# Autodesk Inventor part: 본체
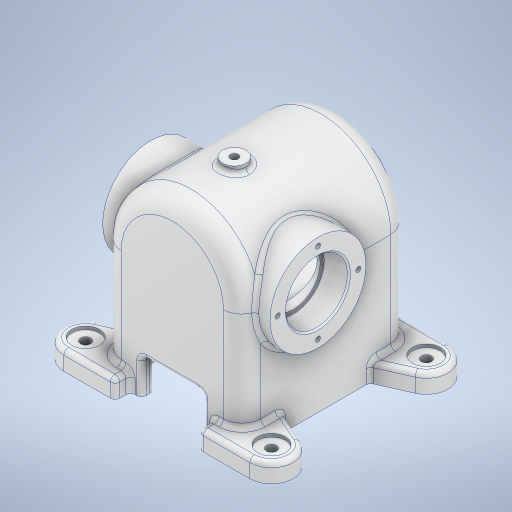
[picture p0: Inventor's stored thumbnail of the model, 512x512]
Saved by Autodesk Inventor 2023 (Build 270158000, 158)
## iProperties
Created: 2024-09
Part Number: 본체
Material: 알루미늄 6061
Document SubType Name: Modeling
Designer: asung
Density: 2.7 g/cm^3
Appearance: 알루미늄 - 평지
Mass: 1380.46 g
Surface Area: 1145.88 cm^2
Volume: 511.281 cm^3
Author: asung
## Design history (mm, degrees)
sketch "스케치1" dims "d0" = 90
  geometry: L1 (-45, 0)-(45, 0); L2 (45, 0)-(45, -76); L3 (45, -76)-(-45, -76); L4 (-45, -76)-(-45, 0); L5 (-20, -76)-(20, -76); L6 (20, -76)-(20, -53); L7 (20, -53)-(-20, -53); L8 (-20, -53)-(-20, -76); 5 further points
  constraints: 16 end point, 4 parallel, 2 horizontal, 2 midpoint, 2 perpendicular, 1 coincident, 1 point on line, 1 vertical, 3 other
  dimensions: "d1" = 90 distance of L2.end L3.end; "d2" = 76 distance of L1.end L2.end; "d3" = 40 distance of L7.end L6.end; "d4" = 23 distance of L6.end L5.end
extrude "돌출1" new body sketch "스케치1" stored distance "d5" = 108; taper "d6" = 0 deg
sketch "스케치2"
  geometry: C1 r 28.5 at (0, 0); 1 further point
  constraints: 1 centre point, 1 coincident
  dimensions: "d7" = 57 diameter of C1
extrude "돌출2" join sketch "스케치2" distance "d8" = 6; taper "d9" = 0 deg
fillet "모깎기1" dims "d10" = 12
fillet "모깎기2" dims "d11" = 3
node "작업 평면1"
sketch "스케치3"
  geometry: L1 (12, 109)-(12, 23) reference; L2 (12, 23)-(-96, 23) reference; L3 (-96, 23)-(-96, 44.5) reference; L4 (-99, 47.5)-(-102, 47.5) reference; L5 (-102, 47.5)-(-102, 104.5) reference; L6 (-102, 104.5)-(-99, 104.5) reference; L7 (-96, 107.5)-(-96, 109) reference; L8 (-84, 121)-(0, 121) reference; L9 (-102, 76)-(12, 76); L10 (3, 76)-(3, 109); L11 (0, 112)-(-84, 112); L12 (-87, 109)-(-87, 76); A1 r 12 centre (0, 109) between (12, 109) and (0, 121) reference; A2 r 3 centre (-99, 44.5) between (-96, 44.5) and (-99, 47.5) reference; A3 r 3 centre (-99, 107.5) between (-99, 104.5) and (-96, 107.5) reference; A4 r 12 centre (-84, 109) between (-84, 121) and (-96, 109) reference; A5 r 3 centre (0, 109) between (3, 109) and (0, 112); A6 r 3 centre (-84, 109) between (-84, 112) and (-87, 109); 1 further point
  constraints: 8 end point, 4 point on circle, 4 tangent, 3 point on line, 2 centre point, 2 perpendicular, 1 equal radius, 1 horizontal, 1 midpoint, 1 vertical
  dimensions: "d12" = 9 distance between parallel lines of L8 L11; "d13" = 9 distance between parallel lines of L10 L1; "d14" = 9 distance from line of L7.end L12; "d15" = 3 radius of A5
revolve "회전1" sketch "스케치3" stored, may be unused: angle "d16" = 90 deg
sketch "스케치4"
  geometry: C1 r 28.5 at (0, 0) reference; 2 further points
  constraints: 1 coincident
hole "구멍1" sketch "스케치4" at (0, 0) diameter "d17" = 33; stored, may be unused: countersink angle "d21" = 90 deg, drill point angle "d23" = 118 deg; dims "d18" = 7, "d19" = 4, "d20" = 2, "d22" = 25
chamfer "모따기1" distance "d24" = 1; stored, may be unused: second distance "d25" = 2, angle "d26" = 45 deg
node "작업 평면2"
sketch "스케치5"
  geometry: L1 (-102, 104.5)-(-102, 47.5) reference; C1 r 31 at (-28, 76)
  constraints: 1 centre point
  dimensions: "d28" = 62 diameter of C1; "d127" = 74 distance from line of L1 C1.centre
extrude "돌출3" join sketch "스케치5" stored distance "d29" = 10; taper "d30" = 0 deg
sketch "스케치9" dims "d60" = 46
  geometry: 3 further points
  constraints: 2 vertical alignment, 1 coincident, 2 other
hole "구멍5" sketch "스케치9" at (0, 23) diameter "d61" = 3.242; stored, may be unused: countersink angle "d65" = 90 deg, drill point angle "d67" = 118 deg; dims "d62" = 8, "d63" = 4, "d64" = 2, "d66" = 10
node "작업 평면3"
sketch "스케치10"
  geometry: L1 (-48.5, -6)-(8.5, -6) reference; C1 r 7.5 at (-20, 68); 1 further point
  constraints: 1 centre point, 1 vertical alignment
  dimensions: "d72" = 15 diameter of C1; "d73" = 74 distance from line of L1 C1.centre
extrude "돌출4" join sketch "스케치10" stored distance "d74" = 10; taper "d75" = 0 deg
fillet "모깎기4" dims "d76" = 3
node "작업 평면4"
sketch "스케치11"
  geometry: L1 (-54, -27.659)-(-54, 27.659) reference; L2 (-54, 27.659)-(-35.496, 27.659) reference; L3 (45, -27.659)-(45, -76) reference; L4 (45, -76)-(20, -76) reference; L5 (20, -76)-(20, -53) reference; L6 (20, -53)-(-20, -53) reference; L7 (-20, -53)-(-20, -76) reference; L8 (-20, -76)-(-45, -76) reference; L9 (-45, -76)-(-45, -27.659) reference; L10 (-45, -27.659)-(-54, -27.659) reference; L11 (-36, -27)-(-36, -76); L12 (36, -27)-(36, -76); L13 (54, 27.659)-(54, -27.659) reference; L14 (54, -27.659)-(45, -27.659) reference; L15 (35.496, 27.659)-(54, 27.659) reference; C1 r 36 at (0, 0) reference; A1 r 45 centre (0, 0) between (-36, -27) and (36, -27); A2 r 45 centre (0, 0) between (35.496, 27.659) and (-35.496, 27.659) reference; 1 further point
  constraints: 4 end point, 2 perpendicular, 2 point on circle, 2 point on line, 1 centre point, 1 coincident
  dimensions: "d78" = 90 diameter of A1; "d79" = 9 distance between parallel lines of L11 L9; "d80" = 9 distance between parallel lines of L3 L12
extrude "돌출5" cut sketch "스케치11" stored distance "d81" = 91; taper "d82" = 0 deg
fillet "모깎기6" dims "d83" = 3
fillet "모깎기7" dims "d84" = 3
sketch "스케치12" dims "d87" = 28
  geometry: L1 (-41, 10)-(107, 10); L2 (107, 10)-(107, -118); L3 (107, -118)-(-41, -118); L4 (-41, -118)-(-41, 10); L5 (-41, 10)-(107, -118); L6 (107, 10)-(-41, -118); L7 (53, -8.5)-(66, -8.5) reference; L8 (69, -11.5)-(69, -96.5) reference; L9 (66, -99.5)-(53, -99.5) reference; L10 (53, -108)-(53, -99.5) reference; L11 (66, -108)-(53, -108) reference; L12 (78, -96)-(78, -12) reference; L13 (53, 0)-(66, 0) reference; L14 (53, -8.5)-(53, 0) reference; L15 (0, -8.5)-(13, -8.5) reference; L16 (13, -8.5)-(13, 0) reference; L17 (0, 0)-(13, 0) reference; L18 (-12, -12)-(-12, -96) reference; L19 (13, -108)-(0, -108) reference; L20 (13, -108)-(13, -99.5) reference; L21 (13, -99.5)-(0, -99.5) reference; L22 (-3, -96.5)-(-3, -11.5) reference; L23 (98.693, -16.79)-(78, -26); L24 (33, 10)-(33, -118); L25 (-32.693, -16.79)-(-12, -26); L26 (107, -54)-(-41, -54); L27 (98.693, -91.21)-(78, -82); L28 (-32.693, -91.21)-(-12, -82); L29 (13, 0)-(53, 0) reference; L30 (53, -108)-(13, -108) reference; L31 (53, -8.5)-(53, 10); L32 (13, -8.5)-(13, 10.982); L33 (13, -99.5)-(13, -118); L34 (53, -99.5)-(53, -118); A1 r 3 centre (66, -11.5) between (69, -11.5) and (66, -8.5) reference; A2 r 3 centre (66, -96.5) between (66, -99.5) and (69, -96.5) reference; A3 r 12 centre (66, -96) between (66, -108) and (78, -96) reference; A4 r 12 centre (66, -12) between (78, -12) and (66, 0) reference; A5 r 12 centre (0, -12) between (0, 0) and (-12, -12) reference; A6 r 12 centre (0, -96) between (-12, -96) and (0, -108) reference; A7 r 3 centre (0, -96.5) between (-3, -96.5) and (0, -99.5) reference; A8 r 3 centre (0, -11.5) between (0, -8.5) and (-3, -11.5) reference; 17 further points
  constraints: 32 end point, 9 symmetric about line, 6 midpoint, 5 point on line, 3 horizontal, 3 perpendicular, 3 vertical, 2 parallel, 13 other
  dimensions: "d85" = 148 distance of L2.end L3.end; "d86" = 128 distance of L1.end L2.end; "d88" = 14 distance from line of point (93, -4) L1; "d89" = 36 distance from line of L23.end L1
extrude "돌출6" join sketch "스케치12" distance "d90" = 12; taper "d91" = 0 deg
sketch "스케치13"
  geometry: L1 (27, 12)-(40, 12) reference; L2 (40, 12)-(40, 23) reference; L3 (40, 23)-(80, 23) reference; L4 (80, 23)-(80, 12) reference; L5 (80, 12)-(93, 12) reference; L6 (93, 76)-(93, 12) reference; L7 (27, 12)-(27, 76) reference; L8 (15, 12)-(27, 12) reference; L9 (27, 12)-(27, 76) reference; L10 (15.381, 76)-(27, 76) reference; L11 (15, 62.696)-(15, 12) reference; L12 (93, 12)-(105, 12) reference; L13 (105, 12)-(105, 62.696) reference; L14 (104.619, 76)-(93, 76) reference; L15 (93, 76)-(93, 12) reference; L16 (33, 12)-(87, 12); L17 (87, 12)-(87, -13.735); L18 (87, -13.735)-(33, -13.735); L19 (33, -13.735)-(33, 12); A1 r 33 centre (60, 76) between (93, 76) and (27, 76) reference; 4 further points
  constraints: 8 end point, 2 parallel, 1 horizontal, 1 perpendicular, 1 point on line, 2 other
  dimensions: "d92" = 18 distance between parallel lines of L19 L11; "d93" = 18 distance between parallel lines of L17 L13; "d94" = 25.73479 distance between parallel lines of L16 L18
extrude "돌출7" cut sketch "스케치13" distance "d95" = 10; taper "d96" = 0 deg
fillet "모깎기8" dims "d97" = 3
fillet "모깎기10" dims "d99" = 3
fillet "모깎기11" dims "d100" = 3
node "작업 평면6"
  node "작업 평면5"
sketch "스케치14"
  geometry: L1 (-28.5, -60)-(28.5, -60) reference; C1 r 7.5 at (0, 14); 1 further point
  constraints: 1 centre point, 1 vertical alignment
  dimensions: "d102" = 15 diameter of C1; "d103" = 74 distance from line of L1 C1.centre
extrude "돌출8" join sketch "스케치14" stored distance "d104" = 10; taper "d105" = 0 deg
fillet "모깎기12" dims "d106" = 3
sketch "스케치15"
  geometry: C1 r 7.5 at (0, 0) reference; 2 further points
  constraints: 1 coincident
hole "구멍6" sketch "스케치15" at (0, 0) diameter "d107" = 5.1881; stored, may be unused: countersink angle "d111" = 90 deg, drill point angle "d113" = 118 deg; dims "d108" = 200, "d109" = 4, "d110" = 2, "d112" = 16
sketch "스케치16"
  geometry: A1 r 14 centre (93, 104) between (98.693, 91.21) and (93, 118) reference; A2 r 14 centre (-27, 104) between (-27, 118) and (-32.693, 91.21) reference; A3 r 14 centre (-27, 4) between (-32.693, 16.79) and (-27, -10) reference; A4 r 14 centre (93, 4) between (93, -10) and (98.693, 16.79) reference; 5 further points
  constraints: 4 coincident
hole "구멍7" sketch "스케치16" at (93, 104), (-27, 104), (-27, 4), (93, 4) diameter "d114" = 6.6; stored, may be unused: countersink angle "d118" = 90 deg, drill point angle "d120" = 118 deg; dims "d115" = 12, "d116" = 18, "d117" = 2, "d119" = 12
fillet "모깎기13" dims "d121" = 3
sketch "스케치17"
  geometry: L1 (60, -76)-(74, -76) reference; 3 further points
  constraints: 1 vertical alignment, 1 other
  dimensions: "d122" = 35 distance from line of L1 point (0, -41)
feature "엠보싱1" sketch "스케치17" dims "d10" = 12, "d123" = 0.5, "d124" = 0
fillet "모깎기14" dims "d125" = 3
fillet "모깎기15" dims "d126" = 3
fillet "모깎기16" dims "d128" = 3
sketch "스케치18"
  geometry: C1 r 31 at (0, 0) reference; 2 further points
  constraints: 1 coincident
hole "구멍8" sketch "스케치18" at (0, 0) diameter "d129" = 35; stored, may be unused: countersink angle "d133" = 90 deg, drill point angle "d135" = 118 deg; dims "d130" = 6, "d131" = 40, "d132" = 16, "d134" = 200
sketch "스케치19"
  geometry: C1 r 31 at (0, 0) reference; 2 further points
  constraints: 1 coincident
hole "구멍9" sketch "스케치19" at (0, 0) diameter "d136" = 35; stored, may be unused: countersink angle "d140" = 90 deg, drill point angle "d142" = 118 deg; dims "d137" = 6, "d138" = 40, "d139" = 16, "d141" = 200
chamfer "모따기3" distance "d143" = 1; stored, may be unused: second distance "d144" = 2, angle "d145" = 45 deg
sketch "스케치20" dims "d146" = 52
  geometry: C1 r 31 at (0, 0) reference; 3 further points
  constraints: 2 vertical alignment, 1 coincident, 2 other
hole "구멍10" sketch "스케치20" at (0, 26) diameter "d147" = 3.242; stored, may be unused: countersink angle "d151" = 90 deg, drill point angle "d153" = 118 deg; dims "d148" = 8, "d149" = 40, "d150" = 16, "d152" = 10
node "솔리드1"
mirror "미러1"
pattern_circular "원형 패턴2" dims angle "d69" = 360 deg
mirror "미러3"
pattern_circular "원형 패턴3" dims angle "d155" = 360 deg
mirror "미러4"
node "투영된 루프1"
node "투영된 루프2"
node "투영된 루프3"
node "투영된 루프4"
node "투영된 루프5"
node "절단 모서리 투영1"
node "절단 모서리 투영2"
feature "A9D066F2-1C7D-4E18-AEED-F7BC21143FA4" dims "d17" = 33, "d18" = 7, "d19" = 4, "d20" = 2, "d21" = 90 deg, "d22" = 25, "d23" = 118 deg
other parameters: "d27" = -54, "d71" = -125, "d101" = -4
